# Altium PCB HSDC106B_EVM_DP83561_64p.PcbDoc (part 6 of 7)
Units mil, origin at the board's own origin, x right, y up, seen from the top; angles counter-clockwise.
Board outline 8750.24 x 6394.7 mil, 6 copper layers (Top Layer, GND1, SIG1, SIG2, GND2, Bottom Layer), stack 60.4 mil thick; 472 components, 324 nets, 1622 pads, 1086 vias.
Unrouted connection lines stored in the file: 1.
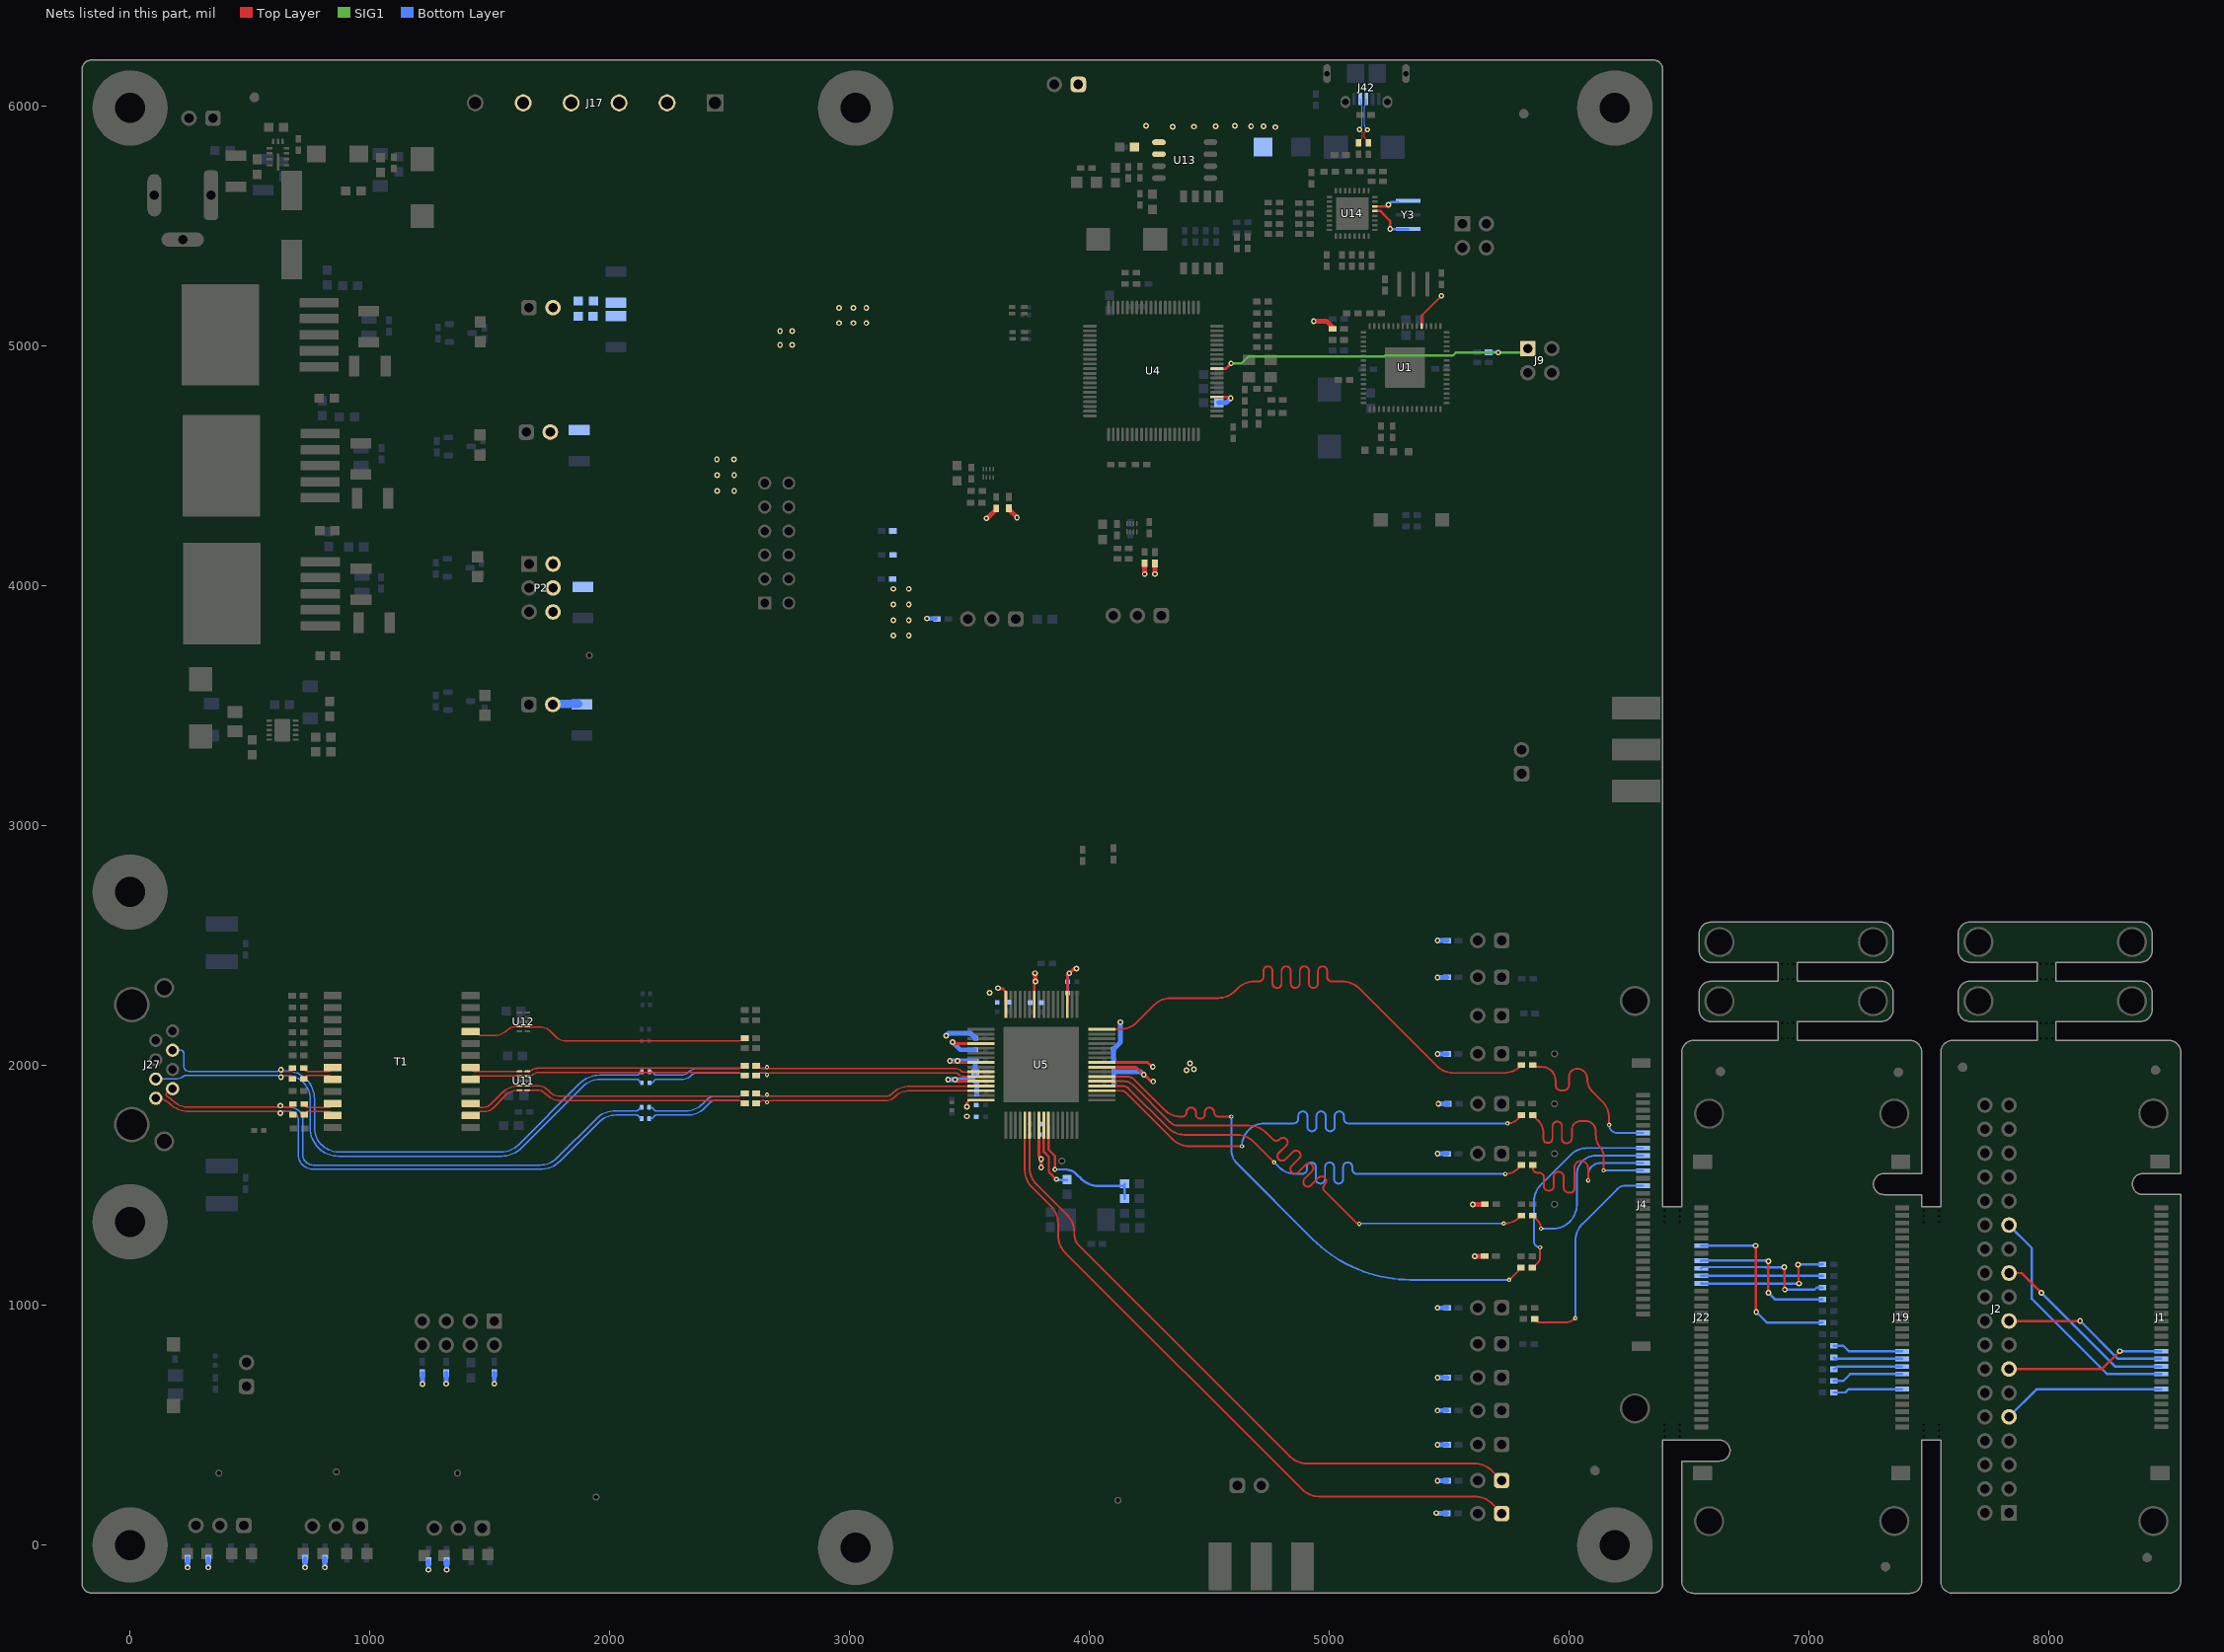
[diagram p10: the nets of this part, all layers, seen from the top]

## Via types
v1: diameter 24, hole 12, Top Layer to Bottom Layer, tented both sides, 903 vias
v2: diameter 24, hole 12, Top Layer to Bottom Layer, 65 vias
v3: diameter 18, hole 7.87, Top Layer to Bottom Layer, tented both sides, 53 vias
v4: diameter 22, hole 10, Top Layer to Bottom Layer, tented both sides, 43 vias
v5: diameter 19.68, hole 7.87, Top Layer to Bottom Layer, 21 vias
v6: diameter 22, hole 12, Top Layer to Bottom Layer, tented both sides, 1 vias

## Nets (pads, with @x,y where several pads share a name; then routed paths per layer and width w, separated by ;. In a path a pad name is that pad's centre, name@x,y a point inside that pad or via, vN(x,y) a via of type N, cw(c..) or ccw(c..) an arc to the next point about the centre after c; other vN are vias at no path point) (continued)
TD_B_x_P: R127.1 T1.9 U12.4 U12.7 | length 1181.4
  Top Layer w6: T1.9@1419.86,2141.7 1433.94,2141.7 cw(c1433.94,2121.28) 1448.38,2135.72 1454.36,2129.74 1454.36,2129.21 ccw(c1462.84,2137.7) 1462.84,2125.7 1521.32,2125.7 ccw(c1521.32,2195.56) 1570.69,2146.13 cw(c1608.44,2108.44) 1570.78,2146.22 cw(c1608.44,2108.44) 1608.44,2161.79 1623.28,2161.79 U12.4@1624.13,2162.63 ccw(c1626.16,2164.66) 1626.16,2161.79 1665.07,2161.79 cw(c1665.07,2160.44) 1666.02,2161.39 ccw(c1666.97,2162.34) 1666.97,2161 1711.08,2161 cw(c1711.08,2107.47) 1748.94,2145.32 1773.73,2120.53 ccw(c1817,2163.8) 1816.89,2102.61 ccw(c1817,2163.8) 1817,2102.61 2532.38,2102.61 ccw(c2532.38,2143.25) 2535.49,2102.72 ccw(c2532.38,2143.25) 2561.12,2114.51 R127.1@2562.84,2114.51
TD_C_cap_N: C104.1 R140.1 | length 409
  Bottom Layer w6: 2173.22,1927.61 ccw(c2173.22,1937.11) 2179.94,1930.39 2185.2,1935.65 ccw(c2183.34,1937.5) 2185.97,1937.5 cw(c2188.59,1937.5) 2186.74,1939.36 cw(c2193.37,1932.73) 2190.36,1941.61 cw(c2193.37,1932.73) 2193.37,1942.11 2300.77,1942.11 ccw(c2300.77,1996.16) 2339,1957.94 ; 2339.03,1957.97 cw(c2366.89,1930.11) 2366.89,1969.51 2533.28,1969.51 ; 2534.03,1969.7 cw(c2534.03,1928.73) R140.1@2562.17,1958.51 ; R140.1@2559.84,1958.51 R140.1@2562.17,1958.51 ; R140.1@2563,1957.7 ccw(c2534.03,1928.73) R140.1@2562.17,1958.51 ; R140.1@2563.03,1958.51 R140.1@2562.17,1958.51
TD_C_cap_P: C103.1 R138.1 | length 409
  Bottom Layer w6: 2173.22,1974.61 cw(c2173.22,1965.1) 2179.94,1971.82 2185.2,1966.56 cw(c2183.34,1964.71) 2185.97,1964.71 ccw(c2188.59,1964.71) 2186.74,1962.85 ccw(c2193.37,1969.48) 2193.37,1960.11 2300.73,1960.11 ccw(c2300.73,1996.28) 2326.3,1970.7 ; 2326.33,1970.73 cw(c2366.84,1930.23) 2366.84,1987.51 2533.28,1987.51 ; 2534.03,1987.7 ccw(c2534.03,2028.67) R138.1@2561.76,1998.51 ; R138.1@2559.84,1998.51 R138.1@2561.76,1998.51 ; R138.1@2563,1999.7 cw(c2534.03,2028.67) R138.1@2561.76,1998.51 ; R138.1@2563.03,1998.51 R138.1@2561.76,1998.51
TD_C_mag_N: R115.2 T1.20 | length 137.2
  Top Layer w6: R115.2@725,1943 cw(c739.7,1943) 739.7,1957.7 828.66,1957.7 cw(c828.66,1941.7) T1.20@844.66,1941.7
TD_C_mag_P: R116.2 T1.19 | length 137.5
  Top Layer w6: R116.2@725,1991 ccw(c740.3,1991) 740.3,1975.7 828.66,1975.7 ccw(c828.66,1991.7) T1.19@844.66,1991.7
TD_C_N: R139.2 R140.2 U5.11 | length 1001.8
  Top Layer w6: R139.2@2610.28,1958.51 cw(c2638.38,1930.38) 2638.38,1970.14 2640.09,1970.14 cw(c2640.09,1947.88) v3@2655.83,1963.62 ; v3(2655.83,1961.52) cw(c2675.11,1942.24) 2675.11,1969.51 3442.18,1969.51 cw(c3442.18,1954.47) 3452.81,1965.11 ; 3452.84,1965.08 ccw(c3477.51,1989.74) 3477.51,1954.86 3545.67,1954.86 cw(c3545.67,1951.98) U5.11@3547.71,1954.01
  Bottom Layer w6: R140.2@2610.28,1958.51 ccw(c2610.28,1968.02) 2617,1961.29 2618.54,1962.84 cw(c2634.65,1946.72) 2634.65,1969.51 2647.84,1969.51 cw(c2647.84,1961.52) v3(2655.83,1961.52)
TD_C_P: R137.2 R138.2 U5.10 | length 999.3
  Top Layer w6: R137.2@2610.28,1998.51 2612.4,1998.51 ccw(c2638.38,2028.62) 2638.38,1988.85 2640.09,1988.85 ccw(c2640.09,2011.12) v3@2655.83,1995.37 ; v3(2655.83,1993.4) ccw(c2670.04,2007.61) 2670.04,1987.51 3442.24,1987.51 cw(c3442.24,1954.63) 3465.49,1977.88 3465.54,1977.83 ccw(c3477.55,1989.85) 3477.55,1972.86 3545.67,1972.86 ccw(c3545.67,1975.73) U5.10@3547.71,1973.7
  Bottom Layer w6: R138.2@2610.28,1998.51 cw(c2610.28,1989.01) 2617,1995.73 2618.54,1994.19 ccw(c2634.65,2010.3) 2634.65,1987.51 2649.94,1987.51 ccw(c2649.94,1993.4) v3(2655.83,1993.4)
TD_C_RJ_N: C104.2 J27.3 R115.1 | length 2464.5
  Top Layer w6: v1(629.38,1951.06) cw(c636.31,1951.06) 636.31,1958 663.38,1958 cw(c663.38,1944) R115.1@677.38,1944
  Bottom Layer w6: J27.3@107.44,1943.64 190.32,1943.64 ccw(c190.32,1992.68) 222.14,1955.36 ; 217.62,1951.94 cw(c232.26,1937.3) 222.14,1955.36 ; v1(629.38,1951.06) cw(c629.38,1962.82) 621.06,1954.51 ccw(c612.63,1946.07) 612.63,1958 232.26,1958 ccw(c232.26,1937.3) 222.14,1955.36 ; v1@629.38,1959 651.79,1959 cw(c651.79,1859.79) 751,1859.79 751,1740 ccw(c869,1740) 869,1622 1548.64,1622 ccw(c1548.64,1739.86) 1631.98,1656.52 1888.27,1912.82 cw(c1958.98,1842.11) 1958.98,1942.11 2111.48,1942.11 cw(c2111.48,1927.61) 2125.98,1927.61
TD_C_RJ_P: C103.2 J27.6 R116.1 | length 2459.1
  Top Layer w6: v1(629.38,1982.94) ccw(c636.31,1982.94) 636.31,1976 663.38,1976 ccw(c663.38,1990) R116.1@677.38,1990
  Bottom Layer w6: J27.6@177.52,2064.11 211.04,2064.11 cw(c211.04,2051.48) 223.67,2051.48 223.67,1997.33 ccw(c245,1997.33) 245,1976 612.63,1976 ccw(c612.63,1987.93) 621.06,1979.49 cw(c629.38,1971.18) v1(629.38,1982.94) ; v1@629.38,1977 651.79,1977 cw(c651.79,1859.79) 769,1859.79 769,1740 ccw(c869,1740) 869,1640 1548.58,1640 ccw(c1548.58,1740) 1619.29,1669.29 1875.58,1925.58 cw(c1958.94,1842.22) 1958.94,1960.11 2111.48,1960.11 ccw(c2111.48,1974.61) 2125.98,1974.61
TD_C_x_N: R139.1 T1.5 U11.2 U11.9 | length 1150.2
  Top Layer w6: T1.5@1419.86,1941.7 cw(c1435,1941.7) 1435,1956.84 1622.09,1956.84 cw(c1622.09,1953.97) U11.2@1624.13,1956 1624.97,1956.84 1656.16,1956.84 U11.9@1657,1956 ; U11.9@1666.49,1956.84 ccw(c1666.49,1974.84) 1679.19,1962.09 cw(c1699.98,1941.31) 1699.98,1970.7 2533.6,1970.7 cw(c2533.6,1929.08) R139.1@2563.03,1958.51
TD_C_x_P: R137.1 T1.6 U11.1 U11.10 | length 1159.3
  Top Layer w6: T1.6@1419.86,1991.7 ccw(c1436.72,1991.7) 1436.72,1974.84 1622.09,1974.84 ccw(c1622.09,1977.72) U11.1@1624.13,1975.68 ccw(c1624.97,1975.68) 1624.97,1974.84 U11.10@1654,1974.84 ; U11.10@1654.01,1975.68 U11.10@1657,1975.68 1666.18,1975.68 1667.23,1976.1 ccw(c1665.04,1981.69) 1668.28,1976.63 ccw(c1665.04,1981.69) 1669,1977.17 cw(c1699.98,1941.31) 1695.32,1988.47 1697.6,1988.7 2539.35,1988.7 ccw(c2539.35,2022.2) R137.1@2563.03,1998.51
TD_D_cap_N: C107.1 R144.1 | length 422.6
  Bottom Layer w6: 2172.22,1778.61 ccw(c2172.22,1788.11) 2178.94,1781.39 2184.2,1786.65 ccw(c2182.34,1788.5) 2184.97,1788.5 cw(c2187.59,1788.5) 2185.74,1790.36 cw(c2192.37,1783.73) 2187.29,1791.61 cw(c2192.37,1783.73) 2192.37,1793.11 2325.98,1793.11 ccw(c2325.98,1888.8) 2393.65,1821.13 2417.86,1845.35 cw(c2439.53,1823.68) 2439.53,1854.32 2533.32,1854.32 ; 2534.06,1854.51 cw(c2534.06,1813.54) R144.1@2562.2,1843.32 ; R144.1@2559.87,1843.32 R144.1@2562.2,1843.32 ; R144.1@2563.03,1842.51 ccw(c2534.06,1813.54) R144.1@2562.2,1843.32 ; R144.1@2563.06,1843.32 R144.1@2562.2,1843.32
TD_D_cap_P: C106.1 R142.1 | length 421.9
  Bottom Layer w6: 2172.22,1825.61 cw(c2172.22,1816.1) 2178.94,1822.82 2184.2,1817.56 cw(c2182.34,1815.71) 2184.97,1815.71 ccw(c2187.59,1815.71) 2185.74,1813.85 ccw(c2192.37,1820.48) 2192.37,1811.11 2318.53,1811.11 ccw(c2318.53,1906.8) 2386.19,1839.13 2405.13,1858.08 cw(c2439.53,1823.68) 2439.53,1872.32 2533.32,1872.32 ; 2534.06,1872.51 ccw(c2534.06,1913.48) R142.1@2561.79,1883.32 ; R142.1@2559.87,1883.32 R142.1@2561.79,1883.32 ; R142.1@2563.06,1883.32 R142.1@2561.79,1883.32 ; R142.1@2563.03,1884.51 cw(c2534.06,1913.48) R142.1@2561.79,1883.32
TD_D_mag_N: R112.2 T1.23 | length 134.4
  Top Layer w6: R112.2@726.62,1795 cw(c739.32,1795) 739.32,1807.7 828.66,1807.7 cw(c828.66,1791.7) T1.23@844.66,1791.7
TD_D_mag_P: R113.2 T1.22 | length 134.8
  Top Layer w6: R113.2@726.62,1839 ccw(c739.92,1839) 739.92,1825.7 828.66,1825.7 ccw(c828.66,1841.7) T1.22@844.66,1841.7
TD_D_N: R143.2 R144.2 U5.14 | length 1005.9
  Top Layer w6: R143.2@2610.28,1842.51 2612.76,1842.51 cw(c2640.87,1814.38) 2640.87,1854.15 2642.57,1854.15 cw(c2642.57,1831.88) 2657.7,1848.22 ccw(c2673.9,1828.45) v3(2655.83,1846.53) cw(c2672.58,1829.78) 2672.58,1853.46 3150.71,1853.46 ccw(c3150.71,1905.07) 3187.21,1868.58 ; 3187.24,1868.61 cw(c3252.88,1802.97) 3252.88,1895.8 3545.67,1895.8 cw(c3545.67,1892.93) U5.14@3547.71,1894.96 cw(c3545.67,1892.93) U5.14@3547.71,1894.96
  Bottom Layer w6: R144.2@2610.28,1841.54 cw(c2638.38,1813.41) 2638.38,1853.17 2639.78,1853.17 cw(c2639.78,1830.48) v3@2652.43,1849.32
TD_D_P: R141.2 R142.2 U5.13 | length 1003.6
  Top Layer w6: R141.2@2612.76,1884.49 ccw(c2640.87,1912.62) 2640.87,1872.85 2642.57,1872.85 ccw(c2642.57,1895.12) v3@2656.5,1877.75 ; v3(2655.83,1878.4) ccw(c2672.58,1895.15) v3@2656.5,1877.75 ; U5.13@3547.71,1914.64 cw(c3545.67,1916.68) 3545.67,1913.8 3252.74,1913.8 ccw(c3252.74,1803.32) 3174.61,1881.44 3174.51,1881.34 cw(c3150.67,1905.19) 3150.67,1871.46 2672.58,1871.46 cw(c2672.58,1895.15) v3@2656.5,1877.75
  Bottom Layer w6: R142.2@2610.28,1883.51 ccw(c2638.38,1911.65) 2636,1871.95 2640.26,1871.95 ccw(c2640.26,1893.97) v3(2655.83,1878.4)
TD_D_RJ_N: C107.2 J27.1 R112.1 | length 2395.7
  Top Layer w6: J27.1@107.44,1863.32 112.83,1863.32 cw(c112.83,1792.36) 162.97,1842.57 ; 163.01,1842.54 ccw(c246.39,1925.92) 246.39,1808 620.06,1808 cw(c620.06,1801.06) v1(627,1801.06) cw(c633.94,1801.06) 633.94,1808 666.38,1808 cw(c666.38,1795) R112.1@679.38,1795
  Bottom Layer w6: v1(627,1801.06) cw(c633.94,1801.06) 633.94,1808 666.5,1808 cw(c666.5,1772.5) 702,1772.5 702,1629.07 ccw(c764.07,1629.07) 764.07,1567 1709.18,1567 ccw(c1709.18,1684.86) 1792.52,1601.52 1954.82,1763.82 cw(c2025.53,1693.11) 2025.53,1793.11 2110.48,1793.11 cw(c2110.48,1778.61) 2124.98,1778.61
TD_D_RJ_P: C106.2 J27.2 R113.1 | length 2408.7
  Top Layer w6: 154.24,1871.1 cw(c157.08,1876.38) 151.31,1874.74 cw(c166.48,1879.11) 150.69,1879.11 150.69,1879.45 cw(c174.72,1879.45) 174.72,1903.48 J27.2@177.52,1903.48 ccw(c177.52,1889.22) J27.2@167.44,1899.3 ; 154.28,1871.07 cw(c112.83,1792.36) 156.47,1869.88 ; 156.48,1869.88 cw(c112.83,1792.36) 166.48,1863.32 cw(c112.83,1792.36) 175.6,1855.4 ; R113.1@679.38,1839 cw(c666.38,1839) 666.38,1826 633.94,1826 cw(c633.94,1832.94) v1(627,1832.94) cw(c620.06,1832.94) 620.06,1826 246.42,1826 cw(c246.42,1926) 175.72,1855.28 ; 175.6,1855.4 cw(c112.83,1792.36) 175.72,1855.28 ; 175.6,1855.4 175.72,1855.28
  Bottom Layer w6: v1(627,1832.94) ccw(c633.94,1832.94) 633.94,1826 666.5,1826 cw(c666.5,1772.5) 720,1772.5 720,1629.07 ccw(c764.07,1629.07) 764.07,1585 1709.12,1585 ccw(c1709.12,1685) 1779.83,1614.29 1942.12,1776.58 cw(c2025.48,1693.22) 2025.48,1811.11 2110.48,1811.11 ccw(c2110.48,1825.61) 2124.98,1825.61
TD_D_x_N: R143.1 T1.2 U11.5 U11.6 | length 1196.3
  Top Layer w6: T1.2@1419.86,1791.7 1425.48,1791.7 ccw(c1425.48,1832.54) 1454.36,1803.66 1454.36,1804.19 T1.2@1456.12,1805.94 ; T1.2@1456.13,1805.95 cw(c1460.36,1801.7) 1460.36,1807.7 1477.79,1807.7 ccw(c1477.79,1855.78) 1511.78,1821.78 1563.53,1873.53 cw(c1622.09,1814.97) 1610.66,1896.99 cw(c1622.09,1814.97) 1622.09,1897.79 cw(c1622.09,1894.91) U11.5@1624.13,1896.94 U11.6@1657,1896.94 cw(c1659.03,1894.91) 1659.03,1897.79 1696.23,1897.79 cw(c1696.23,1848.23) 1731.27,1883.27 1736.96,1877.59 ccw(c1793.87,1934.51) 1744.01,1871.31 ccw(c1793.87,1934.51) 1793.75,1854.01 ccw(c1793.87,1934.51) 1793.87,1854.01 2539.51,1854.01 cw(c2539.51,1824.99) 2560.03,1845.51 R143.1@2563.03,1842.51
TD_D_x_P: R141.1 T1.3 U11.4 U11.7 | length 1195.9
  Top Layer w6: T1.3@1419.86,1841.7 1425.48,1841.7 cw(c1425.48,1800.86) 1454.36,1829.74 1454.36,1829.21 1456.12,1827.46 ccw(c1460.36,1831.7) 1460.36,1825.7 1474.06,1825.7 ccw(c1474.06,1864.78) 1501.68,1837.14 1550.85,1886.31 cw(c1622.02,1815.13) 1622.02,1915.79 1622.09,1915.79 ccw(c1622.09,1918.66) U11.4@1624.13,1916.63 U11.7@1657,1916.63 ccw(c1659.03,1918.66) 1659.03,1915.79 1696.31,1915.79 cw(c1696.31,1848.42) 1743.94,1896.06 1749.59,1890.41 ccw(c1794,1934.81) 1760.98,1881.39 ccw(c1794,1934.81) 1793.89,1872.01 ccw(c1794,1934.81) 1794,1872.01 2539.51,1872.01 ccw(c2539.51,1901.03) 2560.03,1880.51 R141.1@2563.03,1883.51
TEST/SBWTCK: J9.1 R9.2 U4.71 | length 1373.7
  Top Layer w10: U4.71@4531.24,4906.31 4568.98,4906.31 v4(4590.28,4927.61)
  SIG1 w10: v4(4590.28,4927.61) 4633.12,4927.61 4663.34,4957.83 5229.82,4957.83 5232.77,4960.77 5515.07,4960.77 5528,4973.7 v4(5704,4973.7) 5811.69,4973.7 J9.1@5827.6,4989.61
  Bottom Layer w10: R9.2@5661.62,4974.7 R9.2@5664.22,4974.7 5703,4974.7 v4(5704,4973.7)
TX_CTRL: R31.1 U5.48 | length 2510
  Top Layer w8: U5.48@4051.41,2150.87 4127.08,2150.86 ccw(c4127.08,2250.86) 4197.79,2180.15 4269.9,2252.27 cw(c4340.61,2181.55) 4340.61,2281.55 4536.13,2281.55 ccw(c4536.13,2381.55) 4606.84,2310.84 4617.41,2321.41 cw(c4688.12,2250.7) 4633.74,2334.62 cw(c4688.12,2250.7) 4688.12,2350.7 4702,2350.7 4706,2350.7 ccw(c4706,2369.7) 4725,2369.7 4725,2394.59 cw(c4744,2394.59) 4763,2394.59 4763,2342.49 ccw(c4782,2342.49) 4801,2342.49 4801,2394.59 cw(c4820,2394.59) 4839,2394.59 4839,2342.49 ccw(c4858,2342.49) 4877,2342.49 4877,2394.59 cw(c4896,2394.59) 4915,2394.59 4915,2342.49 ccw(c4934,2342.49) 4953,2342.49 4953,2394.59 cw(c4972,2394.59) 4991,2394.59 4991,2369.7 ccw(c5010,2369.7) 5010,2350.7 5048.91,2350.7 5054.58,2350.7 cw(c5054.58,2250.7) 5125.29,2321.41 5448.33,1998.37 ccw(c5519.04,2069.08) 5519.04,1969.08 5727.43,1969.08 ccw(c5727.43,2069.08) 5798.14,1998.37 R31.1@5801.34,2001.57
TX_CTRL_1: J1.50 J2.9 | length 683.6
  Bottom Layer w10: J2.9@7833.6,534.61 7949.78,650.79 J1.50@8469.11,650.79
TX_CTRL_2: J22.50 R207.1 | length 799.8
  Top Layer w10: v1(6777.6,1248.61) 6779.1,1247.11 6779.1,974.11 v1(6780.6,972.61)
  Bottom Layer w10: J22.50@6550.68,1248.82 6550.89,1248.61 v1(6777.6,1248.61) ; v1(6780.6,972.61) 6780.6,971.59 6824.31,927.88 R207.1@7056.98,927.88
TX_CTRL_CS: J4.50 R31.2 | length 767.2
  Top Layer w8: R31.2@5848.59,2001.57 ccw(c5866.63,2019.62) 5866.63,1994.1 5887.15,1994.1 cw(c5887.15,1938.13) 5943.11,1938.13 5943.11,1918.89 ccw(c5965.51,1918.89) 5965.51,1896.49 5977.8,1896.49 ccw(c5977.8,1917.44) 5998.75,1917.44 5998.75,1951.75 cw(c6034,1951.75) 6034,1987 cw(c6034,1946) 6075,1946 ccw(c6152.25,1946) 6097.63,1891.37 6137.31,1851.69 cw(c6066.6,1780.98) 6166.6,1780.98 v3(6166.6,1752.72)
  Bottom Layer w8: v3(6166.6,1752.72) ccw(c6200.11,1752.72) 6200.11,1719.21 J4.50@6308.86,1719.21
TX_CTRL_LP: J19.50 R130.2 | length 290.2
  Bottom Layer w10: R130.2@7104.22,636.61 7151.41,636.61 7165.5,650.7 J19.50@7388.6,650.7
TX_D0: R29.1 U5.38 | length 2292.9
  Top Layer w8: U5.38@4051.41,1954.01 4159.01,1954.01 cw(c4159.01,1918.58) 4184.05,1943.65 4311.7,1816 ccw(c4382.41,1886.71) 4382.41,1786.71 4386.41,1786.71 ccw(c4386.41,1805.71) 4405.41,1805.71 4405.41,1805.85 cw(c4424.41,1805.85) 4443.41,1805.85 4443.41,1797.06 ccw(c4462.41,1797.06) 4481.41,1797.06 4481.41,1805.85 cw(c4500.41,1805.85) 4519.41,1805.85 4519.41,1805.71 ccw(c4538.41,1805.71) 4538.41,1786.71 4567.28,1786.71 v3(4591.46,1786.71) ; v3(5749.69,1106.49) ccw(c5749.69,1109.25) 5751.65,1107.3 R29.1@5801.34,1157
  Bottom Layer w8: v3(4591.46,1786.71) 4591.46,1647.64 ccw(c4670.56,1647.64) 4614.63,1591.7 4930.05,1276.27 4930.1,1276.23 ccw(c5339.88,1686.01) 5339.88,1106.49 5339.93,1106.49 v3(5749.69,1106.49)
TX_D0_1: J1.46 J2.25 | length 1016.9
  Bottom Layer w10: J2.25@7833.6,1334.61 7929.6,1238.61 7929.6,1026.61 8242.42,713.78 J1.46@8469.11,713.78
TX_D0_2: J22.46 R206.1 | length 650
  Top Layer w10: v1(6830.6,1052.61) v1(6830.6,1183.61)
  Bottom Layer w10: J22.46@6550.68,1185.83 6551.07,1186.22 6827.99,1186.22 v1(6830.6,1183.61) ; v1(6830.6,1052.61) 6858.24,1024.97 R206.1@7056.98,1024.97
TX_D0_LP: J19.46 R132.2 | length 296.2
  Bottom Layer w10: R132.2@7104.22,685.15 7143.64,685.15 7172.18,713.69 J19.46@7388.6,713.69
TX_D1: R27.1 U5.37 | length 2437.5
  Top Layer w8: U5.37@4051.41,1934.33 4144.09,1934.33 cw(c4144.09,1882.66) 4180.63,1919.2 4336.13,1763.7 ccw(c4371.64,1799.21) 4371.64,1748.99 4666.25,1748.99 cw(c4666.25,1648.99) 4736.96,1719.7 4762.33,1694.33 4765.16,1691.5 ccw(c4778.59,1704.94) 4792.03,1691.5 4793.73,1693.2 cw(c4807.17,1679.77) 4820.6,1693.2 cw(c4807.17,1679.77) 4820.6,1666.33 4789.57,1635.3 ccw(c4803.01,1621.87) 4789.57,1608.43 ccw(c4803.01,1621.87) 4816.44,1608.43 4847.47,1639.46 cw(c4860.91,1626.03) 4874.34,1639.46 cw(c4860.91,1626.03) 4874.34,1612.59 4843.31,1581.56 ccw(c4856.75,1568.13) 4843.31,1554.69 ccw(c4856.75,1568.13) 4870.18,1554.69 4901.21,1585.72 cw(c4914.65,1572.29) 4928.08,1585.72 cw(c4914.65,1572.29) 4928.08,1558.85 4897.05,1527.82 ccw(c4910.49,1514.39) 4897.05,1500.95 ccw(c4910.49,1514.39) 4923.92,1500.95 4954.95,1531.98 cw(c4968.39,1518.55) 4981.82,1531.98 cw(c4968.39,1518.55) 4981.82,1505.11 4980.12,1503.41 ccw(c4993.55,1489.98) 4980.12,1476.54 5004.56,1452.1 5110.76,1345.9 ccw(c5125,1360.14) v3(5125,1340) ; v3(5727.21,1341.26) ccw(c5727.21,1441.26) 5797.92,1370.55 R27.1@5801.34,1373.98
  Bottom Layer w8: v3@5125,1341.26 v3(5727.21,1341.26)
TX_D1_1: J1.44 J2.21 | length 796.8
  Top Layer w10: J2.21@7833.6,1134.61 7886.6,1134.61 v1(7968.6,1052.61)
  Bottom Layer w10: v1(7968.6,1052.61) 8275.93,745.28 J1.44@8469.11,745.28
TX_D1_2: J22.44 R205.1 | length 603.5
  Top Layer w10: v1(6896.16,1159.17) 6897.88,1157.45 6897.88,1067.32 v1(6899.6,1065.61)
  Bottom Layer w10: J22.44@6550.68,1154.33 6555.52,1159.17 6819.86,1159.17 6820.3,1158.73 6895.73,1158.73 v1(6896.16,1159.17) ; v1(6899.6,1065.61) 7023.48,1065.61 7031.39,1073.51 R205.1@7056.98,1073.51
TX_D1_LP: J19.44 R134.2 | length 289.1
  Bottom Layer w10: R134.2@7104.22,733.7 7108,733.7 7119.49,745.19 J19.44@7388.6,745.19
TX_D2: R25.1 U5.36 | length 2251.7
  Top Layer w8: U5.36@4051.41,1914.64 4138,1914.64 cw(c4138,1878.3) 4163.69,1904.01 4327.62,1740.08 ccw(c4396.56,1809.02) 4327.66,1740.04 ccw(c4396.56,1809.02) 4396.56,1711.52 4613.34,1711.52 cw(c4613.34,1611.52) 4684.05,1682.23 v3(4770,1596.28) ; v3(5733.38,1547.87) ccw(c5733.38,1622.06) 5785.85,1569.6 R25.1@5801.34,1585.09
  Bottom Layer w8: v3(4770,1596.28) 4789.13,1577.16 ccw(c4859.84,1647.87) 4859.84,1547.87 4883,1547.87 4887,1547.87 ccw(c4887,1566.87) 4906,1566.87 4906,1577.04 cw(c4925,1577.04) 4944,1577.04 4944,1526.66 ccw(c4963,1526.66) 4982,1526.66 4982,1577.04 cw(c5001,1577.04) 5020,1577.04 5020,1526.66 ccw(c5039,1526.66) 5058,1526.66 5058,1577.04 cw(c5077,1577.04) 5096,1577.04 5096,1566.87 ccw(c5115,1566.87) 5115,1547.87 5140.12,1547.87 v3(5733.38,1547.87)
TX_D2_1: J1.42 J2.17 | length 700.9
  Top Layer w10: J2.17@7833.6,934.61 v1(8130.6,934.61)
  Bottom Layer w10: v1(8130.6,934.61) 8288.43,776.77 J1.42@8469.11,776.77
TX_D2_2: J22.42 R204.1 | length 507.6
  Bottom Layer w10: J22.42@6550.68,1122.83 6550.79,1122.72 7056.32,1122.72 R204.1@7056.98,1122.06 R204.1@7056.25,1121.33
TX_D2_LP: J19.42 R135.2 | length 286.7
  Bottom Layer w10: R135.2@7104.22,782.24 7109.78,776.69 J19.42@7388.6,776.69
TX_D3: R23.1 U5.35 | length 2241
  Top Layer w8: U5.35@4051.41,1894.96 4134.57,1894.96 cw(c4134.57,1872.82) 4150.22,1888.48 4345.8,1692.9 ccw(c4416.51,1763.61) 4416.51,1663.61 v3(4635.6,1663.61) ; v3(5743.06,1758.84) ccw(c5743.06,1816.28) 5783.67,1775.66 R23.1@5801.34,1793.33
  Bottom Layer w8: v3(4635.6,1663.61) cw(c4730.83,1663.61) 4730.83,1758.84 4847.66,1758.84 4851.66,1758.84 ccw(c4851.66,1777.84) 4870.66,1777.84 4870.66,1789.84 cw(c4889.66,1789.84) 4908.66,1789.84 4908.66,1744.79 ccw(c4927.66,1744.79) 4946.66,1744.79 4946.66,1789.84 cw(c4965.66,1789.84) 4984.66,1789.84 4984.66,1744.79 ccw(c5003.66,1744.79) 5022.66,1744.79 5022.66,1789.84 cw(c5041.66,1789.84) 5060.66,1789.84 5060.66,1777.84 ccw(c5079.66,1777.84) 5079.66,1758.84 5102.67,1758.84 v3(5743.06,1758.84)
TX_D3_1: J1.40 J2.13 | length 666.3
  Top Layer w10: J2.13@7833.6,734.61 8222.6,734.61 v1(8296.6,808.61)
  Bottom Layer w10: v1(8296.6,808.61) 8468.77,808.61 J1.40@8469.11,808.27
TX_D3_2: J22.40 R203.1 | length 593.2
  Top Layer w10: v1(6954.1,1170.11) 6956.35,1167.86 6956.35,1092.86 v1(6958.6,1090.61)
  Bottom Layer w10: J22.40@6550.68,1091.34 6551.31,1091.97 6552.68,1090.61 v1(6958.6,1090.61) ; v1(6954.1,1170.11) 7056.48,1170.11 R203.1@7056.98,1170.61
TX_D3_LP: J19.40 R136.2 | length 293.7
  Bottom Layer w10: R136.2@7104.22,830.79 7143.49,830.79 7166.1,808.18 J19.40@7388.6,808.18
TXCLK_CS: J4.36 R20.2 | length 904.2
  Top Layer w8: R20.2@5848.59,942.76 ccw(c5882.35,976.52) 5882.35,928.77 5983.42,928.77 ccw(c5983.42,988.99) v3(6025.98,946.43)
  Bottom Layer w8: v3(6025.98,946.43) 6025.98,1268.78 cw(c6125.98,1268.78) 6055.27,1339.49 6199.91,1484.13 cw(c6235.19,1448.85) 6220.5,1496.53 cw(c6235.19,1448.85) 6235.19,1498.74 J4.36@6308.86,1498.74
TXD0_CS: J4.46 R29.2 | length 865.4
  Top Layer w8: R29.2@5848.59,1157 5872.42,1180.83 ccw(c5857.5,1195.75) 5878.6,1195.75 v3(5878.6,1241.61)
  Bottom Layer w8: v3(5878.6,1241.61) cw(c5878.6,1266.74) 5853.47,1266.74 5853.47,1433.04 cw(c5953.47,1433.04) 5882.76,1503.75 6005.93,1626.93 cw(c6076.64,1556.22) 6076.64,1656.22 J4.46@6308.86,1656.22
TXD1_CS: J4.44 R27.2 | length 720.2
  Top Layer w8: R27.2@5848.59,1373.98 5868.2,1354.36 cw(c5833.45,1319.61) 5876.63,1343.08 cw(c5833.45,1319.61) 5881.48,1330.04 cw(c5833.45,1319.61) v3(5882.6,1319.61)
  Bottom Layer w8: v3(5882.6,1319.61) 5932,1319.61 ccw(c5932,1419.61) 6032,1419.61 6032,1544 cw(c6112.72,1544) 6112.72,1624.72 J4.44@6308.86,1624.72
TXD2_CS: J4.42 R25.2 | length 906.6
  Top Layer w8: R25.2@5848.59,1585.09 5848.59,1572.21 ccw(c5868.2,1572.21) 5868.2,1552.6 5876.89,1552.6 cw(c5876.89,1535.24) 5894.26,1535.24 5894.26,1497.06 ccw(c5912.96,1497.06) 5912.96,1478.35 5917.8,1478.35 ccw(c5917.8,1496.14) 5935.59,1496.14 5935.59,1536.35 cw(c5956.25,1536.35) 5945.85,1554.21 cw(c5956.25,1536.35) 5956.25,1557.02 cw(c5956.25,1535.79) 5977.36,1537.99 cw(c5956.25,1535.79) 5977.48,1535.79 5977.48,1491.67 ccw(c5999.82,1491.67) 5999.82,1469.33 6004.29,1469.33 ccw(c6004.29,1487.76) 6022.72,1487.76 6022.72,1575.72 cw(c6048.82,1575.72) 6048.82,1601.82 cw(c6048.82,1571.6) 6079.04,1571.6 v3(6079.02,1520.88)
  Bottom Layer w8: v3(6079.02,1520.88) 6079.02,1544.82 cw(c6125.38,1544.82) 6092.6,1577.61 cw(c6130.31,1539.89) 6130.31,1593.23 J4.42@6308.86,1593.23
TXD3_CS: J4.40 R23.2 | length 917.1
  Top Layer w8: R23.2@5848.59,1793.33 5869.59,1772.33 cw(c5813.84,1716.58) 5881.7,1756.72 cw(c5813.84,1716.58) 5892.69,1716.58 5892.69,1694.43 ccw(c5909.58,1694.43) 5909.58,1677.54 5912.96,1677.54 ccw(c5912.96,1695.11) 5930.53,1695.11 5930.53,1746.91 cw(c5949.46,1746.91) 5949.46,1765.84 5951.88,1765.84 cw(c5951.88,1747.98) 5969.73,1747.98 5969.73,1692.63 ccw(c5985.88,1692.63) 5985.88,1676.48 5990.08,1676.48 ccw(c5990.08,1697.46) 6011.06,1697.46 6011.06,1731.56 cw(c6047.71,1731.56) 6047.71,1768.21 6068.56,1768.21 cw(c6068.56,1725.42) 6111.36,1725.42 6111.36,1710.46 ccw(c6195.34,1710.46) 6129,1658.96 cw(c6093.77,1623.72) 6134.08,1653.01 cw(c6093.77,1623.72) 6143.6,1623.72 v3(6143.6,1562.61)
  Bottom Layer w8: v3(6143.6,1562.61) ccw(c6145.71,1564.72) 6145.71,1561.73 J4.40@6308.86,1561.73
USB_N: J42.2 R181.1 | length 201.8
  Top Layer w5: R181.1@5122,5848.62 cw(c5131.51,5848.62) 5124.78,5855.34 5134.68,5865.24 ccw(c5127.42,5872.5) 5137.69,5872.5 5137.69,5891.06 ccw(c5125.38,5891.06) v4(5125.38,5903.37)
  Bottom Layer w5: v4(5125.38,5903.37) cw(c5131.3,5903.37) 5127.12,5907.55 5134.84,5915.28 ccw(c5129.06,5921.07) 5137.24,5921.01 ; J42.2@5129.24,6031.3 5129.24,6018.25 ccw(c5142.89,6018.25) 5133.24,6008.6 cw(c5123.59,5998.95) 5137.24,5998.95 5137.24,5921.01 ; 5137.24,5921.07 cw(c5129.06,5921.07) 5137.24,5921.01
USB_P: J42.3 R182.1 | length 202.8
  Top Layer w5: v4(5159.6,5902.61) ccw(c5159.6,5890.3) 5147.29,5890.3 5147.29,5872.5 ccw(c5157.73,5872.5) 5150.35,5865.12 5160.62,5854.85 cw(c5153.9,5848.13) R182.1@5163.41,5848.13
  Bottom Layer w5: J42.3@5154.83,6031.3 5154.83,6018.25 cw(c5141.19,6018.25) 5150.84,6008.6 ccw(c5160.49,5998.95) 5146.84,5998.95 5146.84,5921.07 ccw(c5159.05,5921.07) 5150.41,5912.43 5159.14,5903.71 cw(c5158.04,5902.61) v4(5159.6,5902.61)
USB_VBUS: C19.2 C110.1 C111.1 D9.1 J21.1 R3.2 U1.53 U4.65 U13.1 U13.2 | length 374.8
  Top Layer w9: U1.53@5384.89,5083.92 5385.08,5084.11 5385.08,5127.91 5467.17,5210 v4(5467.28,5210)
  Top Layer w10: U4.65@4531.24,4788.2 4579.76,4788.2 4585.08,4782.88 v1(4588.87,4782.88)
  Top Layer w20: v1(4935,5104.7) 4988,5104.7 R3.2@5019,5073.7
  Bottom Layer w20: C19.2@4538.76,4764.18 4570.17,4764.18 v1(4588.87,4782.88)
  other v1: 4774.6,5913.61 4347.6,5914.61 4435.6,5915.61 4673.6,5916.61 4725.6,5916.61 4525.6,5917.61 4236.6,5919.61 4606.6,5919.61
VDD1P0: C27.1 C28.2 C29.2 C30.2 C31.2 C32.2 C77.2 J17.2 J24.2 U5.8 U5.41 U5.51 | length 1054.3
  Top Layer w11.2: U5.51@3907.83,2255.08 v1@3907.83,2376.53
  Top Layer w11.8: v1@3456.63,2013.07 U5.8@3547.71,2013.07 ; U5.41@4051.41,2013.07 4242.64,2013.07
  Top Layer w12: 4242.64,2013.07 4260.76,1994.95 v1(4264.01,1994.95)
  Top Layer w13.7: v1(3418,2019.7) 3424.63,2013.07 3456.63,2013.07 v1(3450,2019.7) ; v1@3907.83,2376.53 v1(3916,2384.7) 3935,2403.7 v1(3946,2403.7)
  Bottom Layer w10: C29.2@4100.28,2022.6 C29.2@4101.12,2021.76
  Bottom Layer w11: C32.2@3908.73,2302.41 C31.2@3908.73,2349.36 3908.73,2377.43 v1(3916,2384.7)
  Bottom Layer w20: v1(3418,2019.7) v1(3450,2019.7) 3450.55,2019.15 3523.43,2019.15 3523.98,2018.61 C27.1@3523.98,1971.61 ; C29.2@4100.28,2022.6 C30.2@4100.28,2068.61 4129.45,2097.77 v1(4129.45,2181.1)
  Bottom Layer w35: J24.2@1763,3496.7 1774.96,3508.66 C77.2@1869,3508.66
VDDA1P8: J17.3 J23.2 R97.1 R99.1
VDDA1P8_AB: C38.2 C39.2 C75.2 R97.2 U5.16 | length 80.2
  Top Layer w11: v1(3489,1827.7) 3489,1844.7 3499.89,1855.59 U5.16@3547.71,1855.59
  other v1: 3489,1787.96 2710,5004.7 2761,5004.7 2710,5062.7 2761,5062.7
VDDA1P8_CD: C36.2 C37.2 C76.2 R99.2 U5.64 | length 92.9
  Top Layer w11: v1(3618,2322.87) 3621.17,2319.7 3640,2319.7 3651.92,2307.78 U5.64@3651.92,2255.08
  other v1: 3584,2303.7 2956,5096.7 3016,5096.7 3070,5096.7 2956,5159.7 3016,5159.7 3070,5159.7
VDDA2P5: C26.2 C33.2 C34.2 C35.2 C74.2 J17.4 J20.2 U5.4 U5.12 | length 638
  Top Layer w11.8: v1@3434.89,2091.81 U5.4@3547.71,2091.81 ; 3455.38,1934.33 U5.12@3547.71,1934.33
  Top Layer w13.7: v1@3410,1935.7 3410,1934.83 v1@3410.13,1934.7 ; v1(3440,1940.7) ccw(c3455.38,1956.08) 3455.38,1934.33
  Bottom Layer w10: C35.2@3528.91,1880.61 C35.2@3529.7,1881.39
  Bottom Layer w20: v1(3402,2124.7) 3403.08,2124.7 3412.99,2134.61 3504.91,2134.61 C33.2@3525.91,2113.61 ; v1(3410,1940.7) v1(3440,1940.7) 3514,1940.7 C34.2@3529.7,1925 C35.2@3529.7,1881.39 ; v1(3429.44,2098.26) 3462.09,2065.61 C26.2@3522.98,2065.61
  other v1: 2447.77,4396.7 2518.77,4396.7 2447.77,4462.7 2518.77,4462.7 2446.77,4527.7 2517.77,4527.7
VDDIO: C40.2 C41.2 C42.2 C43.2 C44.2 C45.2 C84.2 J17.5 P2.2 P2.4 P2.6 R42.2 R43.2 R44.2 R47.2 R48.2 R51.2 R85.1 R86.1 R87.2 R88.1 R89.1 R147.1 R148.2 R151.2 R152.2 R153.2 R155.2 R156.2 R157.1 R159.2 R160.2 R163.2 R164.2 R165.2 R166.1 R167.2 R168.2 R169.2 R172.2 R173.2 U5.24 U5.40 U5.58 | length 1855.9
  Top Layer w11.8: U5.58@3770.03,2255.08 v1@3770.03,2344.73 ; 3789.72,1621.56 U5.24@3789.72,1751.38 ; U5.40@4051.41,1993.38 4192.31,1993.39
  Top Layer w12: 4192.31,1993.39 4224.09,1961.61 v1(4226.6,1961.61) ; v1@4227,1958.7 4231.51,1958.7 4254.2,1936.01 4263.71,1936.01 v1(4266,1933.71)
  Top Layer w13.7: v1@3770.03,2344.73 v1@3776,2350.7 ; 3789.72,1621.56 ccw(c3791.1,1621.56) 3790.12,1620.58 3798.6,1612.1 v1(3798.6,1609.64) v1(3798.6,1575.61)
  Top Layer w20: v1(3570.45,4282.17) 3571.21,4282.94 3575.15,4282.94 3611.45,4319.24 R47.2@3611.45,4323.17 ; R51.2@3663.64,4324.17 3663.64,4320.24 3697.74,4286.13 v1(3697.74,4285.36) ; v1@3774,2351 v1@3774,2385 ; R48.2@4230.1,4094.48 4230.35,4094.23 4230.35,4049.86 v1(4230.6,4049.61) ; v1(4272.6,4049.61) 4272.85,4049.86 4272.85,4093.73 R85.1@4273.1,4093.98 ; v1(5598.81,1421.22) R155.2@5647.18,1421.22 ; v1(5606.49,1205.05) 5645.1,1205.05 R152.2@5647.47,1207.42
  Bottom Layer w10: C43.2@4101.12,1927.77 C43.2@4101.28,1927.61
  Bottom Layer w20: v1(239.5,-93.25) R168.2@239.5,-57.02 ; v1(326.49,-93.28) R166.1@326.49,-57.05 ; v1(729.5,-93.25) R159.2@729.5,-57.02 ; v1(812.5,-93.25) R157.1@812.5,-57.02 ; R89.1@1218.49,717.07 1220.35,715.2 1218.6,713.44 v1(1218.6,671.61) 1219.52,671.61 v1@1220.6,672.69 ; v1(1244.5,-103.25) R148.2@1244.5,-67.02 ; v1(1317.6,672.61) 1317.6,716.18 R88.1@1318.49,717.07 ; v1(1320.5,-103.25) R147.1@1320.5,-67.02 ; R86.1@1518.49,717.07 1517.6,716.18 1518.6,715.18 v1(1518.6,672.61) ; v1(3321.98,3864.39) R87.2@3358.21,3864.39 ; C43.2@4101.12,1927.77 C42.2@4101.12,1973.7 4214.5,1973.7 v1(4226.6,1961.61) ; v1(5446.6,133.61) 5447.1,133.11 5489.48,133.11 R164.2@5489.98,132.61 ; v1(5451.31,268.61) R165.2@5491.31,268.61 ; v1(5451.31,418.62) R167.2@5491.31,418.62 ; v1(5451.31,561.16) R163.2@5491.31,561.16 ; v1(5451.31,698.36) R169.2@5491.31,698.36 ; v1(5451.31,989.59) R160.2@5491.31,989.59 ; v1(5451.31,1631.93) R151.2@5491.31,1631.93 ; v1(5451.31,2048.41) R156.2@5491.31,2048.41 ; v1(5451.31,2367.87) R173.2@5491.31,2367.87 ; v1(5451.31,2521) R172.2@5491.31,2521 ; v1(5455.02,1840.17) R153.2@5495.02,1840.17
  other v1: 4404.51,1980.8 4435.92,1983.89 4419.43,2008.83 3774.5,2351 3773.5,2385 3182,3792.7 3247,3792.7 3182,3857.7 3247,3857.7 3182,3922.7 3247,3922.7 3182,3987.7 3247,3987.7
VDDIOSEL_0: J36.1 U5.22 | length 2736.1
  Top Layer w8: U5.22@3750.35,1751.38 3750.35,1574.5 ccw(c3850.35,1574.5) 3779.64,1503.79 3907.31,1376.12 cw(c3836.6,1305.4) 3936.6,1305.4 3936.6,1297.61 ccw(c4006.61,1297.61) 3957.07,1248.13 ; 3957.1,1248.1 4835.42,369.79 ccw(c4906.13,440.5) 4906.13,340.5 5606.09,340.5 cw(c5606.09,240.5) 5676.8,311.21 J36.1@5718.99,269.01
VDDIOSEL_1: J35.1 U5.21 | length 2850.3
  Top Layer w8: U5.21@3730.66,1751.38 3730.66,1563.78 ccw(c3830.66,1563.78) 3731.33,1552.26 ccw(c3830.66,1563.78) 3759.95,1493.07 3839.71,1413.31 cw(c3769,1342.6) 3869,1342.6 3869,1291.63 ccw(c3969,1291.63) 3898.29,1220.92 4886.93,232.27 ccw(c4957.64,302.98) 4957.64,202.98 5606.26,202.98 cw(c5606.26,102.98) 5676.98,173.69 J35.1@5718.99,131.67
XI: R82.2 R84.2 U5.26 | length 569.2
  Top Layer w10: U5.26@3829.09,1751.38 3829.09,1649.79 3855.6,1623.28 v4(3855.6,1566.61)
  Bottom Layer w10: v4(3855.6,1566.61) 3898.03,1566.61 cw(c3898.03,1498.84) 3945.93,1546.77 3965.8,1526.9 ccw(c4036.52,1597.61) 4036.52,1497.61 R84.2@4146.1,1497.61 ; R82.2@4146.1,1444.98 R84.2@4146.1,1497.61 ; R84.2@4146.1,1506.61 R84.2@4146.1,1497.61
XO: R77.2 U5.25 | length 294.9
  Top Layer w10: U5.25@3809.4,1751.38 3809.4,1640.3 3830.64,1619.06 3830.64,1555.91 v4@3862.41,1524.14
  Bottom Layer w10: v4(3862.04,1525.4) 3864.76,1522.68 R77.2@3906.6,1522.68
XTAL1: U14.30 Y3.1 | length 103.8
  Top Layer w9: U14.30@5189.9,5583.03 5208.67,5583.03
  Top Layer w10: 5208.67,5583.03 5240.33,5583.03 v1(5247,5589.7)
  Bottom Layer w10: v1(5247,5589.7) 5259,5601.7 Y3.1@5286,5601.7
XTAL2: U14.29 Y3.3 | length 190.5
  Top Layer w10: U14.29@5189.9,5563.35 5189.98,5563.27 5212.84,5563.27 5253.6,5522.51 v1(5253.6,5488.61)
  Bottom Layer w10: v1(5253.6,5488.61) 5253.75,5488.45 5329.3,5488.45 Y3.3@5329.46,5488.29
pads on no net: FID1.1 FID2.1 FID3.1 FID4.1 FID5.1 FID6.1 FID7.1 FID8.1 FID9.1 FID10.1 FID11.1 FID12.1 FID13.1 FID14.1 FID15.1 FID16.1 FID17.1 FID18.1 H1.0 H2.0 H3.0 H4.0 H5.0 H6.0 H7.0 H8.0 J1.2 J1.4 J1.11 J1.14 J1.17 J1.27 J1.33 J1.53 J1.55 J1.57 J1.59 J4.2 J4.4 J4.11 J4.14 J4.17 J4.27 J4.33 J4.53 J4.55 J4.57 J4.59 J19.2 J19.4 J19.11 J19.14 J19.17 J19.27 J19.33 J19.53 J19.55 J19.57 J19.59 J22.2 J22.4 J22.11 J22.14 J22.17 J22.27 J22.33 J22.53 J22.55 J22.57 J22.59 J42.4 U1.3 U1.4 U1.5 U1.6 U1.7 U1.8 U1.10 U1.12 U1.13 U1.18 U1.19 U1.22 U1.23 U1.24 U1.25 U1.26 U1.27 U1.28 U1.29 U1.30 U1.31 U1.34 U1.35 U1.36 U1.41 U1.42 U1.45 U1.46 U1.47 U1.48 U1.60 U1.61 U1.62 U1.63 U4.5 U4.6 U4.7 U4.8 U4.9 U4.10 U4.12 U4.13 U4.15 U4.16 U4.17 U4.25 U4.26 U4.27 U4.29 U4.30 U4.31 U4.32 U4.33 U4.34 U4.35 U4.36 U4.39 U4.40 U4.41 U4.42 U4.43 U4.44 U4.45 U4.48 U4.53 U4.54 U4.55 U4.56 U4.57 U4.58 U4.59 U4.60 U4.72 U4.73 U4.74 U4.75 U5.1 U5.7 U5.9 U5.17 U5.18 U5.19 U5.20 U6.8 U11.3@1624.13,1936.31 U11.8@1657,1936.31 U12.3@1624.13,2182.31 U12.8@1657,2182.31 U14. U14.5 U14.9 U14.13 U14.17 U14.21 U14.32

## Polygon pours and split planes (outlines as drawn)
GND on Top Layer "GND_L01_P838" (solid, remove dead copper, pour order 838): 22 vertices, not listed, extent 43.57,-161.88 6562.57,6146.56
no net on Top Layer "Top Layer-No Net 3" (solid, pour order 833): 2858.14,3875.14
no net on Top Layer "Top Layer-No Net 4" (solid, pour order 832): 2858,3875.29 2858.29,3875
no net on Top Layer "Top Layer-No Net 5" (solid, pour order 831): 2858.14,3875.14
no net on Top Layer "Top Layer-No Net 1" (solid, pour order 830): 2907.19,3820 3285,3820
no net on Top Layer "Top Layer-No Net 2" (solid, pour order 829): 2907.19,3820
no net on Top Layer "Top Layer-No Net" (solid, pour order 828): 2805,4052.47
GND on Top Layer "Bottom Layer-No Net" (solid, remove dead copper, pour order 783): 3668.51,4936.7 3608,4936.7 3602,4942.7 3602,5329.7 3608,5335.7 3697,5335.7 3705,5327.7 3705,4942.7 3699,4936.7
GND_2 on Top Layer "GND_2" (solid, remove dead copper, pour order 813): 27 vertices, not listed, extent 6502,-169 7453,2087
RJ45_ERTH on Top Layer "Bottom Layer-No Net" (solid, remove dead copper, pour order 827): -160,1186.2 -115.4,1141.61 111.6,1141.61 187.6,1217.61 187.6,1490.61 213.6,1517.35 480.62,1517.35 529,1565.73 529,1621.64 529,2418.64 485.36,2462.28 -110.72,2462.28 -160,2413
GND_1 on Top Layer "GND_2" (solid, remove dead copper, pour order 814): 17 vertices, not listed, extent 7582,-160 8512,2066
5V on Top Layer "5V_L01_P803" (solid, remove dead copper, pour order 803): 928.6,5710.61 900.6,5738.61 900.6,5886.61 912.6,5898.61 1296.6,5898.61 1314.6,5880.61 1314.6,5681.61 1276.6,5643.61 1191.6,5643.61 1122.6,5574.61 946.6,5574.61 928.6,5592.61
VDDA1P8_AB on Top Layer "VDDA1P8_AB_L01_P757" (solid, remove dead copper, pour order 757): 3492.23,1861.63 3475.52,1844.92 3475.52,1781.05 3489,1767.57 3582.45,1767.57 3608.52,1793.64 3608.52,1854.47 3599.31,1863.68 3495.18,1863.68 3493.87,1862.37
GND on Top Layer "GND_L01_P810" (solid, remove dead copper, pour order 810): 17 vertices, not listed, extent 3449.65,4371.32 3561.6,4467.61
MCU_VCC on Top Layer "Bottom Layer-No Net" (solid, remove dead copper, pour order 780): 4006.6,5729.61 4001.6,5734.61 4001.6,5791.61 4011.99,5802 4118.6,5802 4148.99,5771.61 4224.6,5771.61 4320.6,5771.61 4322.6,5769.61 4322.6,5728.61 4321.6,5727.61 4152.6,5727.61 4150.6,5729.61
NetC13_1 on Top Layer "NETC13_1_L01_P811" (solid, remove dead copper, pour order 811): 3522.39,4473.98 3487,4473.98 3433.6,4473.98 3429.9,4477.68 3429.9,4521.91 3435.6,4527.61 3550.98,4527.61 3575.6,4502.98 3575.6,4480.98 3573.6,4478.98 3527.39,4478.98
no net on Top Layer "NONET_L01_P809" (solid, pour order 809): 4726.6,5216.61
MCU_VCC on Top Layer "MCU_VCC_L01_P808" (solid, remove dead copper, pour order 808): 4726.6,5216.61 4807.6,5216.61 4823.6,5200.61 4823.6,5028.61 4809.6,5014.61 4727.13,5014.61 4721.6,5020.14 4721.6,5210.13
no net on Top Layer "NONET_L01_P807" (solid, pour order 807): 4735.38,5186.61
GND on Top Layer "GND_L01_P806" (solid, remove dead copper, pour order 806): 19 vertices, not listed, extent 4059.6,4131.61 4159.6,4242.61
NetC14_1 on Top Layer "NETC14_1_L01_P805" (solid, remove dead copper, pour order 805): 4126.41,4242.61 4083,4242.61 4078,4237.61 4034.6,4237.61 4027.6,4244.61 4027.6,4284.61 4030.6,4287.61 4155.6,4287.61 4171.6,4271.61 4171.6,4249.61 4169.6,4247.61 4131.41,4247.61
USB_VBUS on Top Layer "USB_VBUS_L01_P804" (solid, remove dead copper, pour order 804): 19 vertices, not listed, extent 3913.6,5782.2 4885.6,6134.7
1V8 on Top Layer "Bottom Layer-No Net" (solid, pour order 761): 19 vertices, not listed, extent 701,5091.7 1703,5347.7
5V on Top Layer "Bottom Layer-No Net" (solid, remove dead copper, pour order 778): 28 vertices, not listed, extent 223.6,3274.61 594,3447.7
NetC56_2 on Top Layer "NETC56_2_L01_P787" (solid, remove dead copper, pour order 787): 18 vertices, not listed, extent 608.98,5727.61 825.6,5840.57
no net on Top Layer "NONET_L01_P788" (solid, pour order 788): 640.22,5828.09
5V-36V on Top Layer "5V-36V_L01_P743" (solid, remove dead copper, pour order 743): 20 vertices, not listed, extent 595.6,5528.61 788.6,5786.61
5V-36V on Top Layer "5V-36V_L01_P747" (solid, remove dead copper, pour order 747): 405.6,5880.61 497.6,5880.61 564.6,5813.61 589.6,5813.61 592.6,5810.61 592.6,5776.61 590.6,5774.61 563.6,5774.61 534.6,5745.61 409.88,5745.61 396.6,5758.88 396.6,5871.61
5V-36V_jack on Top Layer "5V-36V_JACK_L01_P750" (solid, remove dead copper, pour order 750): 294.6,5968.61 294.6,5542.51 310.82,5526.29 363.62,5526.29 381.27,5543.94 381.27,5967.44 363.1,5985.61 311.6,5985.61
2V5 on Top Layer "Bottom Layer-No Net" (solid, pour order 767): 25 vertices, not listed, extent 707,4511.7 1703,4838.7
3V3 on Top Layer "Bottom Layer-No Net" (solid, pour order 776): 17 vertices, not listed, extent 708,3816.61 1713.83,4162.61
GND on Top Layer "Bottom Layer-No Net" (solid, pour order 782): 798,3634.7 788,3624.7 788,3498.7 793,3493.7 952,3493.7 956,3497.7 956,3624.7 946,3634.7
MCU_VCC on Top Layer "Bottom Layer-No Net" (solid, remove dead copper, pour order 781): 4091.6,5498.61 4091.6,5536.61 4074.6,5553.61 3941.6,5553.61 3906.6,5518.61 3906.6,5359.61 3913.6,5352.61 4089.15,5352.61 4091.6,5355.06 4091.6,5394.61
1V1 on Top Layer "Bottom Layer-No Net" (solid, pour order 777): 20 vertices, not listed, extent 676,3359.7 957,3477.7
GND on Top Layer "Bottom Layer-No Net" (solid, pour order 764): 1144,4973.7 1144,5065.7 1140,5069.7 961,5069.7 951,5059.7 951,4992.7 954,4989.7 1036,4989.7 1037,4988.7 1037,4849.7 1040,4846.7 1138,4846.7 1144,4852.7
5V on Top Layer "Bottom Layer-No Net" (solid, remove dead copper, pour order 785): 897.6,4947.3 897.6,4892.3 829.54,4824.24 829.54,4745.66 842.3,4732.9 978.2,4732.9 988,4742.7 988,4942.7 968,4962.7 913,4962.7
5V on Top Layer "Bottom Layer-No Net" (solid, remove dead copper, pour order 786): 971,3890.7 985,3876.7 985,3667.7 972,3654.7 848.5,3654.7 835.6,3667.61 835.6,3727.3 908,3799.7 908,3873.7 925,3890.7
5V on Top Layer "Bottom Layer-No Net" (solid, remove dead copper, pour order 784): 832.21,4208.7 829,4211.91 829,4266.7 902,4339.7 902,4399.7 912,4409.7 976,4409.7 979,4406.7 979,4221.7 966,4208.7
GND on Top Layer "Bottom Layer-No Net" (solid, pour order 779): 380.09,3448.61 357,3471.7 255,3471.7 236,3490.7 236,3660.7 240,3664.7 479,3664.7 491,3652.7 491,3472.66 466.95,3448.61
GND on Top Layer "Bottom Layer-No Net" (solid, pour order 771): 1048,4519.7 1056,4527.7 1158,4527.7 1165,4520.7 1165,4303.7 1159,4297.7 1149,4297.7 1051,4297.7 1048,4300.7
GND on Top Layer "Bottom Layer-No Net" (solid, pour order 773): 1059,3910.7 1154,3910.7 1159,3905.7 1159,3784.7 1153,3778.7 1055,3778.7 1052,3781.7 1052,3903.7
VDDA1P8_CD on Top Layer "VDDA1P8_CD_L01_P754" (solid, remove dead copper, pour order 754): 3569.04,2326.76 3569.04,2244.57 3615.74,2197.88 3647.98,2197.88 3657.59,2207.49 3657.59,2318.17 3640.85,2334.91 3575.83,2334.91
GND on Bottom Layer "GND_L06_P835" (solid, remove dead copper, pour order 835): 22 vertices, not listed, extent -237.21,-120.9 6281.79,6187.53
VDDIO on Bottom Layer "Bottom Layer-No Net" (solid, pour order 756): 28 vertices, not listed, extent 1720,3769.7 4305.6,4304.61
VDD1P0 on Bottom Layer "VDD1P0_L06_P741" (solid, remove dead copper, pour order 741): 26 vertices, not listed, extent 1722.67,1982.61 4305.94,3589.94
GND on Bottom Layer "GND_L06_P772" (solid, remove dead copper, pour order 772): 3710,1869 3789,1869 3794,1864 3794,1845 3765,1816 3765,1701 3761,1697 3722,1697 3717,1702 3717,1798 3702,1813 3702,1861
5V on Bottom Layer "Bottom Layer-No Net" (solid, remove dead copper, pour order 749): 309,3423.7 240,3423.7 223.6,3407.3 223.6,3292.1 252,3263.7 423.09,3263.7 476,3316.61 476,3418.7 471,3423.7 467,3423.7
GND on Bottom Layer "Bottom Layer-No Net" (solid, pour order 748): 953,3492.7 957,3496.7 957,3623.7 947,3633.7 723,3633.7 713,3623.7 713,3503.7 724,3492.7
1V1 on Bottom Layer "Bottom Layer-No Net" (solid, pour order 746): 23 vertices, not listed, extent 641,3360.7 956,3536.7
5V on Bottom Layer "Bottom Layer-No Net" (solid, pour order 745): 17 vertices, not listed, extent 880.6,5655.61 1351.55,5878.61
VDDIO on Bottom Layer "VDDIO_L06_P740" (solid, remove dead copper, pour order 740): 4339.6,1964.61 4400.6,2025.61 4446.6,2025.61 4451.6,2020.61 4451.6,1926.61 4432.6,1907.61 4101.74,1907.61 4088.6,1920.75 4088.6,1982.61 4094.95,1988.95 4221.25,1988.95 4245.6,1964.61
VDDA1P8_CD on Bottom Layer "VDDA1P8_CD_L06_P739" (solid, remove dead copper, pour order 739): 3569.44,2285.84 3602.68,2252.61 3677.6,2252.61 3677.6,2304.61 3646.62,2335.59 3596.76,2335.59 3569.44,2308.27
VDDIO on Bottom Layer "VDDIO_L06_P738" (solid, remove dead copper, pour order 738): 3775.87,1573.61 3775.87,1769.88 3781.6,1775.61 3826.6,1775.61 3837.64,1764.56 3837.64,1575.39 3820.05,1557.8 3794.6,1557.8
VDDA1P8_AB on Bottom Layer "VDDA1P8_AB_L06_P736" (solid, remove dead copper, pour order 736): 3473,1842.4 3473,1783.57 3482.28,1774.29 3538.9,1774.29 3538.9,1843.1 3532,1850 3480.6,1850
VDDIO on Bottom Layer "VDDIO_L06_P735" (solid, remove dead copper, pour order 735): 3749.44,2395.9 3804.55,2395.9 3815.75,2384.7 3815.75,2254.75 3811,2250 3743.39,2250 3740.79,2252.61 3740.79,2387.25
GND_1 on Bottom Layer "GND_2" (solid, remove dead copper, pour order 774): 17 vertices, not listed, extent 7582,-160 8512,2066
NetJ42_6 on Bottom Layer "Bottom Layer-No Net" (solid, remove dead copper, pour order 759): 20 vertices, not listed, extent 4921,5936.61 5356,6175.7
RJ45_ERTH on Bottom Layer "Bottom Layer-No Net" (solid, remove dead copper, pour order 763): -160,1186.2 -115.4,1141.61 111.6,1141.61 187.6,1217.61 187.6,1490.61 213.6,1517.35 480.62,1517.35 529,1565.73 529,1621.64 529,2418.64 485.36,2462.28 -110.72,2462.28 -160,2413
GND_2 on Bottom Layer "GND_2" (solid, remove dead copper, pour order 775): 27 vertices, not listed, extent 6502,-169 7453,2087
GND on Bottom Layer "GND_L06_P770" (solid, pour order 770): 512.07,1489 553,1448.07 553,1293 512,1252 316,1252 281,1287 281,1465 305,1489
5V-36V_jack on Bottom Layer "5V-36V_JACK_L06_P768" (solid, remove dead copper, pour order 768): 293.6,5985.61 293.6,5536.61 305.93,5524.27 369.96,5524.27 380.29,5534.61 380.29,5982.91 366.62,5996.59 304.58,5996.59
MCU_VCC on Bottom Layer "MCU_VCC_L06_P769" (solid, remove dead copper, pour order 769): 4014.6,5804.61 4155,5804.61 4174.6,5785.01 4174.6,5728.8 4173.41,5727.61 4008.6,5727.61 4001.6,5734.61 4001.6,5791.61
1V8 on Bottom Layer "Bottom Layer-No Net" (solid, pour order 751): 19 vertices, not listed, extent 926,5059.7 1697,5279.7
3V3 on Bottom Layer "Bottom Layer-No Net" (solid, pour order 742): 29 vertices, not listed, extent 918,3703.7 1705,4266.7
5V-36V on Bottom Layer "5V-36V_L06_P737" (solid, remove dead copper, pour order 737): 714.23,5880.61 782.34,5812.5 782.34,5474.69 712.25,5404.61 605.6,5404.61 595.6,5414.61 595.6,5583.61 680.6,5668.61 680.6,5733.58 676.6,5737.58 417.9,5737.58 396.6,5758.88 396.6,5871.61 405.6,5880.61 506.1,5880.61
VDDA1P8 on Bottom Layer "Bottom Layer-No Net" (solid, pour order 753): 1717,5540.7 1942,5765.7 1941,5766.7 1941,6141.7 1951,6151.7 2113,6151.7 2125,6139.7 2125,5581.7 1890,5346.7 1890,5272.7 1891,5271.7 1891,5097.7 1886,5092.7 1727,5092.7 1717,5102.7
NetC116_1 on Bottom Layer "Bottom Layer-No Net" (solid, remove dead copper, pour order 760): 4965.1,5881.11 5023.6,5939.61 5070.15,5986.16 5104.19,5986.16 5114.54,5975.8 5114.54,5918.1 5086.7,5890.26 5086.7,5805.41 5061.4,5780.11 4996.94,5780.11 4916.03,5780.11 4837.03,5780.11 4831.03,5786.11 4831.03,5875.11 4837.03,5881.11
VDDA2P5 on Bottom Layer "Bottom Layer-No Net" (solid, pour order 755): 2594.68,4365.7 2610.5,4365.7 2636,4391.2 2636,4539.92 2600.96,4573.7 2265,4573.7 2130,4708.7 1931,4708.7 1928,4711.7 1728,4711.7 1725,4708.7 1725,4541.7 1735,4531.7 2032,4531.7 2198,4365.7
2V5 on Bottom Layer "Bottom Layer-No Net" (solid, pour order 752): 19 vertices, not listed, extent 912,4516.7 1702,4796.61
VDDA1P8_AB on Bottom Layer "Top Layer-No Net 8" (solid, remove dead copper, pour order 766): 2781,4984.7 2872,4984.7 2875,4987.7 2875,5069.96 2868.26,5076.7 2178,5076.7 2173.92,5076.7 2100.13,5147.61 1912.6,5147.61 1910,5145.01 1910,5105.7 1914,5101.7 2053,5101.7 2170,4984.7
VDDA1P8_CD on Bottom Layer "Top Layer-No Net 8" (solid, remove dead copper, pour order 765): 18 vertices, not listed, extent 1911,5062.7 3109,5226.7
GND on Bottom Layer "Bottom Layer-No Net" (solid, remove dead copper, pour order 762): 5090,4645.7 5094,4641.7 5094,4480.7 5083,4469.7 4914,4469.7 4905,4478.7 4905,4640.7 4910,4645.7
USB_VBUS on Bottom Layer "Bottom Layer-No Net" (solid, pour order 758): 3932,5994.7 4030.02,5994.7 4167.6,5857.12 4167.6,5817.8 4213.29,5772.11 4771.1,5772.11 4791.6,5792.61 4791.6,5947.61 4764.6,5974.61 4287.6,5974.61 4188.5,6073.7 4109.51,6152.7 3924,6152.7 3915,6143.7 3915,6011.7
MCU_VCC on SIG2 "SIG2-MCU_VCC" (solid, remove dead copper, pour order 812): 35 vertices, not listed, extent 3353,4099 5551,5806.03
VDDA1P8_CD on SIG2 "Bottom Layer-No Net" (solid, remove dead copper, pour order 800): 3139.51,3267.14 3703.18,2703.47 3703.18,2328.31 3636.07,2261.2 3570.89,2261.2 3530.46,2301.63 3530.46,2588.77 2916.24,3196.17 2916.24,5152.59 2942.09,5178.45 3090.33,5178.45 3139.51,5129.27
VDDIO on SIG2 "Bottom Layer-No Net" (solid, remove dead copper, pour order 834): 19 vertices, not listed, extent 161.88,-141.84 5964.85,4068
